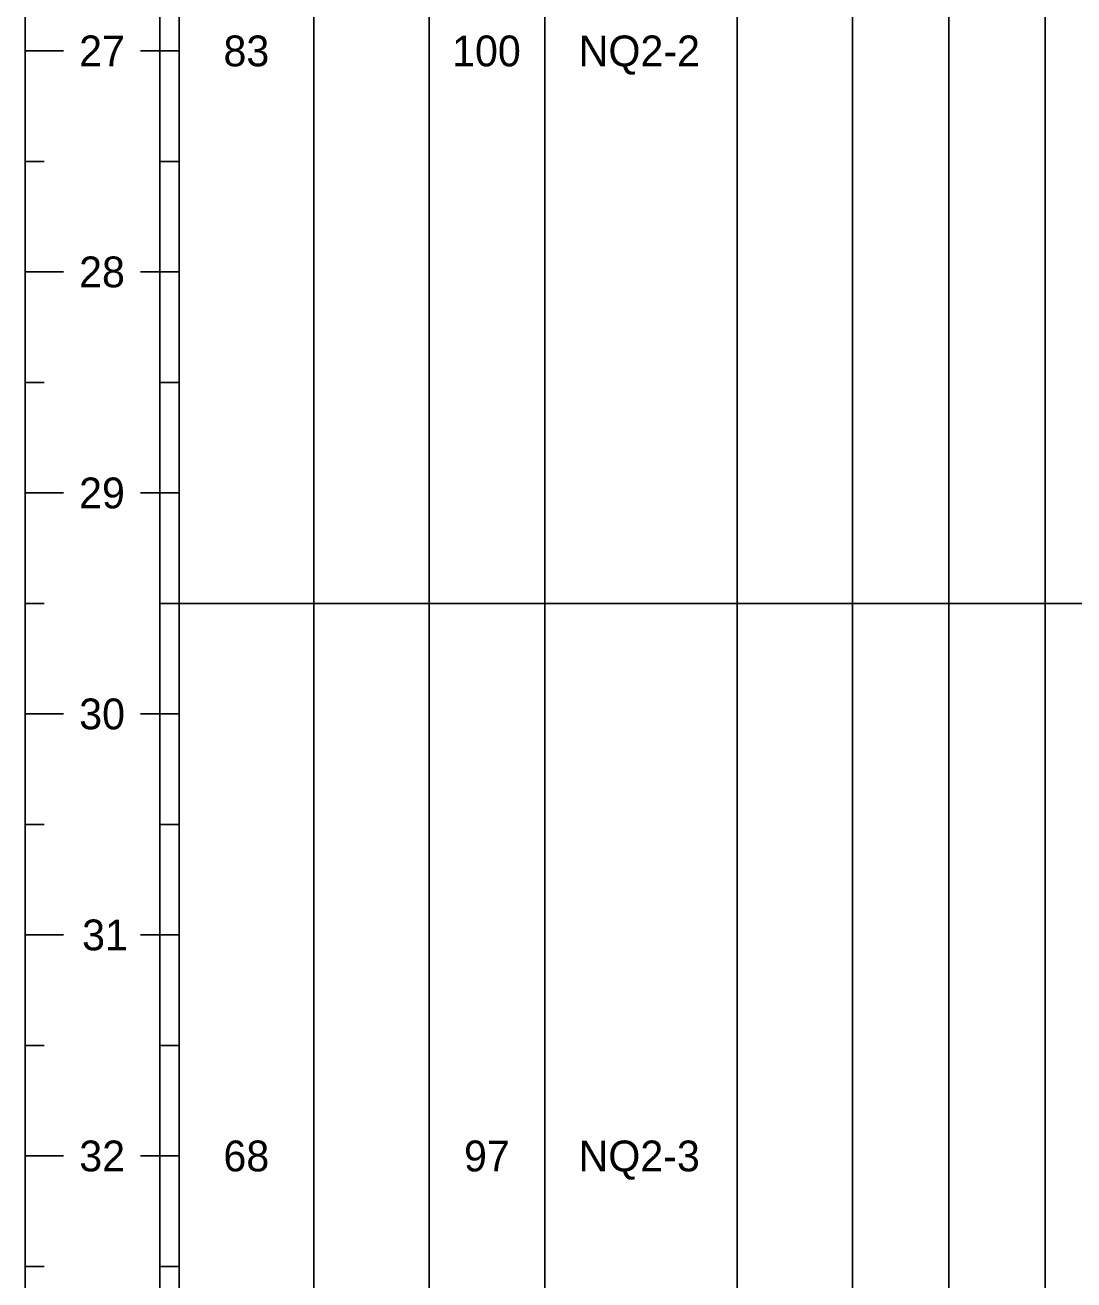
# Model space of a CAD drawing. Extents: x -0.01 to 0.83, y -0.63 to 1.27.
# Drawn here: x 0.3792 to 0.6062, y -0.3617 to -0.0901 of the extents above; entities that cross this region are included whole.
import ezdxf

# ---------------------------------------------------------------- set-up
doc = ezdxf.new("R2010")
doc.units = 0

msp = doc.modelspace()

# ---------------------------------------------------------------- linework, layer by layer
for points in [[(0.4125, 1.22083), (0.4125, -0.62183)], [(0.4125, 1.22083), (0.4125, -0.62183)], [(0.44167, 1.22083), (0.44167, -0.62183)], [(0.46667, 1.22083), (0.46667, -0.62183)], [(0.49167, 1.22083), (0.49167, -0.62183)], [(0.53333, 1.22083), (0.53333, -0.62183)], [(0.55833, 1.22083), (0.55833, -0.62183)], [(0.57917, 1.20833), (0.57917, -0.62183)], [(0.6, 1.20833), (0.6, -0.62183)], [(0.37917, 1.19583), (0.37917, -0.62183)], [(0.40833, 0.02392), (0.40833, -0.21525)], [(0.37917, -0.09567), (0.3875, -0.09567)], [(0.37917, -0.09567), (0.38333, -0.09567)], [(0.4125, -0.09567), (0.40417, -0.09567)], [(0.4125, -0.09567), (0.40833, -0.09567)], [(0.37917, -0.11958), (0.38333, -0.11958)], [(0.4125, -0.11958), (0.40833, -0.11958)], [(0.37917, -0.1435), (0.3875, -0.1435)], [(0.37917, -0.1435), (0.38333, -0.1435)], [(0.4125, -0.1435), (0.40417, -0.1435)], [(0.4125, -0.1435), (0.40833, -0.1435)], [(0.37917, -0.16742), (0.38333, -0.16742)], [(0.4125, -0.16742), (0.40833, -0.16742)], [(0.37917, -0.19133), (0.3875, -0.19133)], [(0.37917, -0.19133), (0.38333, -0.19133)], [(0.4125, -0.19133), (0.40417, -0.19133)], [(0.4125, -0.19133), (0.40833, -0.19133)], [(0.37917, -0.21525), (0.38333, -0.21525)], [(0.40833, -0.21525), (0.4125, -0.21525)], [(0.40833, -0.21525), (0.40833, -0.45442)], [(0.40833, -0.21525), (0.4125, -0.21525)], [(0.4125, -0.21525), (0.40833, -0.21525)], [(0.4125, -0.21525), (0.44167, -0.21525)], [(0.44167, -0.21525), (0.46667, -0.21525)], [(0.46667, -0.21525), (0.49167, -0.21525)], [(0.49167, -0.21525), (0.53333, -0.21525)], [(0.53333, -0.21525), (0.55833, -0.21525)], [(0.55833, -0.21525), (0.57917, -0.21525)], [(0.57917, -0.21525), (0.6, -0.21525)], [(0.6, -0.21525), (0.62083, -0.21525)], [(0.37917, -0.23917), (0.3875, -0.23917)], [(0.37917, -0.23917), (0.38333, -0.23917)], [(0.4125, -0.23917), (0.40417, -0.23917)], [(0.4125, -0.23917), (0.40833, -0.23917)], [(0.37917, -0.26308), (0.38333, -0.26308)], [(0.4125, -0.26308), (0.40833, -0.26308)], [(0.37917, -0.287), (0.3875, -0.287)], [(0.37917, -0.287), (0.38333, -0.287)], [(0.4125, -0.287), (0.40417, -0.287)], [(0.4125, -0.287), (0.40833, -0.287)], [(0.37917, -0.31092), (0.38333, -0.31092)], [(0.4125, -0.31092), (0.40833, -0.31092)], [(0.37917, -0.33483), (0.3875, -0.33483)], [(0.37917, -0.33483), (0.38333, -0.33483)], [(0.4125, -0.33483), (0.40417, -0.33483)], [(0.4125, -0.33483), (0.40833, -0.33483)], [(0.37917, -0.35875), (0.38333, -0.35875)], [(0.4125, -0.35875), (0.40833, -0.35875)]]:
    msp.add_lwpolyline(points)
for points in [[(0.40833, -0.21525), (0.4125, -0.21525), (0.4125, 0.02392), (0.40833, 0.02392)], [(0.40833, -0.45442), (0.4125, -0.45442), (0.4125, -0.21525), (0.40833, -0.21525)]]:
    msp.add_lwpolyline(points, close=True)

# ---------------------------------------------------------------- texts
for s, p in [('27', (0.39087, -0.099)), ('83', (0.42212, -0.099)), ('100', (0.47162, -0.099)), ('NQ2-2', (0.49903, -0.099)), ('28', (0.39086, -0.14683)), ('29', (0.39086, -0.19467)), ('30', (0.39088, -0.2425)), ('31', (0.39151, -0.29033)), ('32', (0.3909, -0.33817)), ('68', (0.42211, -0.33817)), ('97', (0.4742, -0.33817)), ('NQ2-3', (0.499, -0.33817))]:
    msp.add_text(s, height=0.006667).set_placement(p)

doc.saveas('drawing.dxf')
